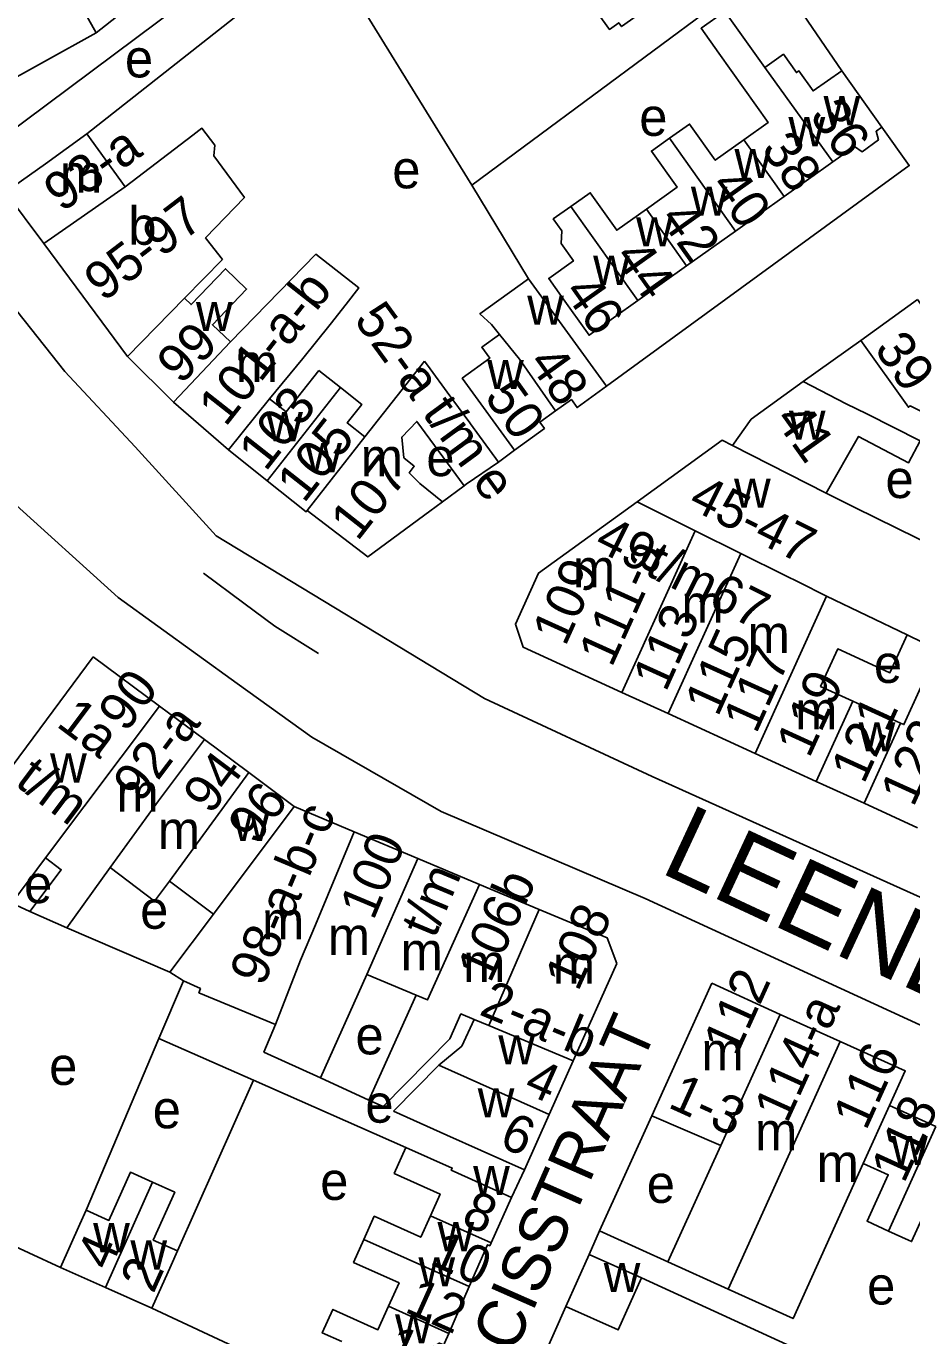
# Model space of a CAD drawing. Extents: x 161141 to 163125, y 381621 to 383200.
# Drawn here: x 162126.8 to 162220.2, y 381774.6 to 381912.6 of the extents above; entities that cross this region are included whole.
import ezdxf

# ---------------------------------------------------------------- set-up
doc = ezdxf.new("R2010")
doc.units = 0
for name, color, linetype in [('BLT_Basislijn', 7, 'Continuous'), ('BLT_Bebouwing', 7, 'Continuous'), ('BLT_Centroide', 7, 'Continuous'), ('BLT_Huisnummer', 7, 'Continuous'), ('BLT_Huisnummer_ tussenligend', 7, 'Continuous'), ('BLT_Huisnummer_reeks', 7, 'Continuous'), ('BLT_Onderverdeling_panden', 7, 'Continuous'), ('BLT_Straatnaam', 7, 'Continuous'), ('BLT_Straatnaam_hoofdweg', 7, 'Continuous')]:
    doc.layers.add(name, color=color, linetype=linetype)

msp = doc.modelspace()

# ---------------------------------------------------------------- linework, layer by layer
at = {"layer": 'BLT_Basislijn'}
for p, q in [((162134.15, 381911.93), (162150.61, 381924.97)), ((162133.2, 381901.27), (162158.24, 381921.04)), ((162205.2, 381919.04), (162212.81, 381907.93)), ((162159.58, 381918.87), (162167.08, 381906.74)), ((162199.23, 381914.71), (162173.8, 381895.86)), ((162167.08, 381906.74), (162173.8, 381895.86)), ((162173.8, 381895.86), (162179.76, 381886.01)), ((162208.74, 381875.18), (162214.81, 381879.51)), ((162176.6, 381866.68), (162178.28, 381867.95)), ((162170.69, 381862.51), (162172.97, 381864.2)), ((162124.99, 381862.81), (162136.48, 381852.42)), ((162146.82, 381858.92), (162175.11, 381841.76)), ((162145.49, 381855), (162149.74, 381851.82)), ((162136.48, 381852.42), (162149.05, 381843.37)), ((162149.74, 381851.82), (162153, 381849.38)), ((162153, 381849.38), (162157.63, 381846.52)), ((162149.05, 381843.37), (162156.93, 381837.69)), ((162156.93, 381837.69), (162170.57, 381829.85)), ((162170.57, 381829.85), (162192.08, 381820.69)), ((162127.17, 381819.34), (162125.26, 381820.19)), ((162192.08, 381820.69), (162221.5, 381807.18)), ((162141.92, 381812.92), (162131.07, 381817.61)), ((162140.78, 381805.93), (162143.37, 381812.03)), ((162133.11, 381787.85), (162140.78, 381805.93)), ((162150.75, 381801.55), (162140.78, 381805.93)), ((162157.82, 381801.79), (162162.94, 381799.43)), ((162150.75, 381801.55), (162142.74, 381783.56)), ((162166.84, 381794.47), (162150.75, 381801.55)), ((162192.77, 381797.81), (162187.27, 381785.66)), ((162177.97, 381789.2), (162179.33, 381792.09)), ((162130.41, 381781.82), (162109.59, 381791.3)), ((162187.27, 381785.66), (162186.16, 381783.18)), ((162209.99, 381772.34), (162191.68, 381780.71)), ((162140.03, 381777.51), (162157.92, 381769.21)), ((162183.71, 381777.7), (162181.23, 381772.15))]:
    msp.add_line(p, q, dxfattribs=at)
for points in [[(162095.04, 381933.46), (162106.52, 381912.88), (162113.22, 381900.94), (162120.76, 381888.92), (162130.87, 381876.22), (162138.27, 381868.29), (162146.82, 381858.92)], [(162121.93, 381899.15), (162152.46, 381921.89), (162150.61, 381924.97)], [(162217.02, 381901.99), (162219.93, 381897.94), (162188, 381874.69)], [(162175.11, 381841.76), (162192.8, 381833.55), (162249.74, 381807.94), (162257.79, 381806.18), (162274.06, 381798.97)], [(162187.27, 381785.66), (162191.82, 381783.6), (162194.48, 381782.39)]]:
    msp.add_lwpolyline(points, dxfattribs=at)
at = {"layer": 'BLT_Bebouwing'}
for p, q in [((162212.81, 381907.93), (162217.02, 381901.99)), ((162133.2, 381901.27), (162137.23, 381895.68)), ((162211.88, 381898.34), (162206.73, 381894.68)), ((162124.62, 381895.15), (162128.65, 381889.71)), ((162206.73, 381894.68), (162201.59, 381891.03)), ((162201.59, 381891.03), (162196.44, 381887.37)), ((162128.65, 381889.71), (162137.46, 381877.82)), ((162147.48, 381888.03), (162143.48, 381883.95)), ((162196.44, 381887.37), (162191.29, 381883.72)), ((162160.54, 381883.33), (162158.86, 381881.18)), ((162214.81, 381879.51), (162220.8, 381883.81)), ((162137.46, 381877.82), (162142.34, 381872.99)), ((162159.93, 381874.54), (162157.64, 381876.33)), ((162168.8, 381877.34), (162162.52, 381869.34)), ((162148.11, 381867.98), (162152.21, 381864.72)), ((162169.36, 381861.53), (162170.69, 381862.51)), ((162211.16, 381863.41), (162214.19, 381861.92)), ((162222.97, 381857.6), (162214.19, 381861.92)), ((162219.71, 381848.47), (162222.96, 381846.9)), ((162133.84, 381846.18), (162140.85, 381840.97)), ((162189.63, 381842.4), (162194.51, 381840.18)), ((162140.85, 381840.97), (162145.58, 381837.45)), ((162213.96, 381841.51), (162219.02, 381839.19)), ((162194.51, 381840.18), (162203.69, 381835.98)), ((162145.58, 381837.45), (162150.28, 381833.98)), ((162203.69, 381835.98), (162210.12, 381833.04)), ((162150.28, 381833.98), (162155.06, 381830.38)), ((162210.12, 381833.04), (162215.19, 381830.73)), ((162215.19, 381830.73), (162220.8, 381828.16)), ((162155.06, 381830.38), (162161.38, 381827.73)), ((162161.38, 381827.73), (162168.08, 381824.92)), ((162128.83, 381824.98), (162125.26, 381820.19)), ((162135.64, 381823.95), (162131.07, 381817.61)), ((162168.08, 381824.92), (162174.6, 381822.19)), ((162141.92, 381812.92), (162146.53, 381819.06)), ((162143.37, 381812.03), (162141.92, 381812.92)), ((162162.72, 381812.7), (162157.82, 381801.79)), ((162167.92, 381810.52), (162162.72, 381812.7)), ((162189.1, 381813.86), (162184.48, 381803.58)), ((162199.09, 381811.76), (162194.07, 381800.68)), ((162206.3, 381808.49), (162199.09, 381811.76)), ((162212.65, 381805.62), (162206.3, 381808.49)), ((162184.48, 381803.58), (162181.94, 381797.92)), ((162194.07, 381800.68), (162192.77, 381797.81)), ((162222.72, 381796.67), (162217.85, 381798.88)), ((162181.94, 381797.92), (162179.33, 381792.09)), ((162192.77, 381797.81), (162200.04, 381794.66)), ((162200.04, 381794.66), (162194.48, 381782.39)), ((162177.97, 381789.2), (162175.82, 381784.41)), ((162186.16, 381783.18), (162183.71, 381777.7)), ((162191.68, 381780.71), (162186.16, 381783.18)), ((162135.14, 381779.7), (162130.41, 381781.82)), ((162140.03, 381777.51), (162135.14, 381779.7)), ((162173.52, 381779.79), (162171.35, 381774.87)), ((162171.35, 381774.87), (162169.17, 381769.92))]:
    msp.add_line(p, q, dxfattribs=at)
for points in [[(162115.41, 381909.1), (162119.78, 381911.54), (162123.36, 381913.53), (162130.92, 381917.74), (162134.15, 381911.93)], [(162199.23, 381914.71), (162197.22, 381917.47), (162196.04, 381916.64), (162195.78, 381917), (162189.58, 381912.59), (162189.29, 381912.99), (162188.3, 381912.29), (162187.12, 381913.92)], [(162202.49, 381900.66), (162205.04, 381902.47), (162199.86, 381909.77), (162197.98, 381912.41), (162200.49, 381914.18), (162204.69, 381908.28)], [(162134.15, 381911.93), (162123.25, 381905.87), (162118.88, 381903.44)], [(162204.69, 381908.28), (162206.66, 381909.67), (162208.03, 381907.74), (162208.29, 381907.92), (162209.79, 381905.81), (162212.81, 381907.93)], [(162133.2, 381901.27), (162128.81, 381898.11), (162124.62, 381895.15)], [(162137.23, 381895.68), (162144.36, 381901.13), (162145.32, 381901.87), (162146.7, 381900.08), (162146.58, 381898.97), (162149.8, 381894.56), (162145.71, 381890.32), (162145.82, 381890.18), (162147.48, 381888.03)], [(162194.64, 381900.81), (162196.75, 381902.31), (162199.46, 381898.5), (162202.49, 381900.66)], [(162217.02, 381901.99), (162216.43, 381901.56), (162216.68, 381900.64), (162214.96, 381899.39), (162214.16, 381899.96), (162211.88, 381898.34)], [(162192.2, 381893.35), (162195.44, 381895.65), (162192.74, 381899.46), (162194.64, 381900.81)], [(162184.25, 381893.64), (162186.28, 381895.08), (162189.08, 381891.13), (162192.2, 381893.35)], [(162184.25, 381893.64), (162182.38, 381892.32), (162183.27, 381891.07), (162183.22, 381889.71), (162184.51, 381887.89), (162181.9, 381886.04), (162183.25, 381884.14), (162186.15, 381880.06), (162191.29, 381883.72)], [(162148.35, 381879.37), (162157.34, 381888.59), (162161.88, 381885.04), (162160.54, 381883.33)], [(162143.48, 381883.95), (162144.17, 381883.29), (162147.82, 381887.06), (162150.03, 381884.93), (162146.42, 381881.17), (162148.35, 381879.37)], [(162176.7, 381880.14), (162175.85, 381881.19), (162174.64, 381882.33), (162179.76, 381886.01)], [(162179.76, 381886.01), (162188, 381874.69)], [(162214.81, 381879.51), (162219.84, 381872.46), (162220.02, 381872.6), (162225.18, 381870.05), (162228.78, 381872.62), (162220.8, 381883.81)], [(162152.46, 381873.35), (162155.95, 381877.62), (162158.86, 381881.18)], [(162178.28, 381867.95), (162172.78, 381875.52), (162175.68, 381877.63), (162174.83, 381878.8), (162176.7, 381880.14)], [(162157.64, 381876.33), (162154.21, 381871.99), (162152.46, 381873.35)], [(162168.8, 381877.34), (162169.39, 381876.53), (162171.2, 381874.05), (162173.57, 381870.82), (162173.64, 381870.72), (162176.6, 381866.68)], [(162208.74, 381875.18), (162203.26, 381871.21), (162201.28, 381868.44)], [(162221.09, 381868.94), (162215.45, 381871.76), (162213.29, 381872.84), (162208.74, 381875.18)], [(162162.52, 381869.34), (162160.65, 381870.81), (162162.18, 381872.76), (162159.93, 381874.54)], [(162182.63, 381872.08), (162184.29, 381873.28), (162184.9, 381872.44), (162188, 381874.69)], [(162142.34, 381872.99), (162148.11, 381867.98)], [(162178.28, 381867.95), (162181.45, 381870.23), (162180.97, 381870.89), (162182.63, 381872.08)], [(162170.69, 381862.51), (162168.29, 381864.45), (162167.19, 381865.56), (162167.71, 381866.25), (162166.62, 381867.14), (162166.4, 381869.33), (162167.98, 381870.98), (162172.97, 381864.2)], [(162211.16, 381863.41), (162214.59, 381869.39), (162219.84, 381866.61), (162221.09, 381868.94)], [(162201.28, 381868.44), (162200.19, 381868.99), (162191.22, 381862.51)], [(162172.97, 381864.2), (162173.18, 381864.35), (162176.6, 381866.68)], [(162152.21, 381864.72), (162156.32, 381861.45), (162156.43, 381861.58)], [(162191.22, 381862.51), (162180.84, 381854.99), (162178.38, 381849.61), (162179.21, 381847.17), (162189.63, 381842.4)], [(162156.43, 381861.58), (162162.83, 381856.69), (162169.36, 381861.53)], [(162219.71, 381848.47), (162217.89, 381844.49), (162215.07, 381845.78)], [(162117.74, 381823.38), (162118.96, 381826.11), (162133.84, 381846.18)], [(162215.07, 381845.78), (162212.38, 381847), (162210.58, 381843.05), (162213.96, 381841.51)], [(162219.02, 381839.19), (162219.37, 381839.03), (162222.96, 381846.9)], [(162127.17, 381819.34), (162130.48, 381823.73), (162128.83, 381824.98)], [(162135.64, 381823.95), (162140.31, 381820.42), (162141.9, 381822.54)], [(162141.9, 381822.54), (162146.53, 381819.06)], [(162174.6, 381822.19), (162180.9, 381819.55)], [(162180.9, 381819.55), (162188.08, 381816.55), (162189.1, 381813.86)], [(162131.07, 381817.61), (162127.17, 381819.34)], [(162153.1, 381807.42), (162145.01, 381810.76), (162145.16, 381811.21), (162143.37, 381812.03)], [(162162.94, 381799.43), (162167.92, 381810.52)], [(162164.45, 381798.76), (162171.46, 381805.91), (162172.64, 381808.54), (162174.03, 381807.96)], [(162157.82, 381801.79), (162151.86, 381804.52), (162153.1, 381807.42)], [(162170.3, 381803.14), (162172.73, 381805.13), (162174.03, 381807.96)], [(162217.85, 381798.88), (162219.5, 381802.52), (162212.65, 381805.62)], [(162165.53, 381798.28), (162170.3, 381803.14)], [(162164.45, 381798.76), (162162.94, 381799.43)], [(162179.33, 381792.09), (162174.77, 381794.14), (162171.16, 381795.76), (162165.53, 381798.28)], [(162166.84, 381794.47), (162165.61, 381791.72), (162170.45, 381789.55), (162169.43, 381787.27)], [(162177.97, 381789.2), (162173.41, 381791.25), (162171.62, 381792.05), (162171.72, 381792.29), (162166.84, 381794.47)], [(162200.83, 381779.52), (162207.67, 381776.42), (162215.08, 381792.77)], [(162215.08, 381792.77), (162217.71, 381791.59), (162215.48, 381786.68), (162217.73, 381785.65)], [(162133.11, 381787.85), (162135.51, 381786.78), (162137.78, 381791.84), (162140.12, 381790.79)], [(162140.12, 381790.79), (162142.46, 381789.74), (162140.19, 381784.7), (162142.74, 381783.56)], [(162217.73, 381785.65), (162219.84, 381784.69), (162220.17, 381784.54), (162222.4, 381789.48), (162224.74, 381788.44)], [(162130.41, 381781.82), (162132.46, 381786.39), (162133.11, 381787.85)], [(162169.43, 381787.27), (162168.41, 381785), (162163.49, 381787.21), (162162.4, 381784.77)], [(162162.4, 381784.77), (162161.31, 381782.34), (162166.11, 381780.19), (162165, 381777.72)], [(162175.82, 381784.41), (162175.68, 381784.1), (162175.46, 381784.2), (162173.52, 381779.79)], [(162142.74, 381783.56), (162142.08, 381782.07), (162140.03, 381777.51)], [(162194.48, 381782.39), (162200.83, 381779.52)], [(162183.71, 381777.7), (162189.23, 381775.23), (162191.68, 381780.71)], [(162160.07, 381774), (162158.02, 381774.92), (162159.13, 381777.39), (162163.89, 381775.25), (162165, 381777.72)]]:
    msp.add_lwpolyline(points, dxfattribs=at)
at = {"layer": 'BLT_Onderverdeling_panden'}
for p, q in [((162211.88, 381898.34), (162204.69, 381908.28)), ((162201.59, 381891.03), (162194.64, 381900.81)), ((162206.73, 381894.68), (162202.49, 381900.66)), ((162128.65, 381889.71), (162137.23, 381895.68)), ((162191.29, 381883.72), (162184.25, 381893.64)), ((162196.44, 381887.37), (162192.2, 381893.35)), ((162137.46, 381877.82), (162143.48, 381883.95)), ((162148.35, 381879.37), (162142.34, 381872.99)), ((162159.93, 381874.54), (162152.21, 381864.72)), ((162152.46, 381873.35), (162148.11, 381867.98)), ((162162.52, 381869.34), (162156.43, 381861.58)), ((162211.16, 381863.41), (162201.28, 381868.44)), ((162197.34, 381859.45), (162191.22, 381862.51)), ((162189.63, 381842.4), (162197.34, 381859.45)), ((162202.15, 381857.05), (162197.34, 381859.45)), ((162194.51, 381840.18), (162202.15, 381857.05)), ((162203.69, 381835.98), (162211.21, 381852.55)), ((162211.21, 381852.55), (162219.71, 381848.47)), ((162128.83, 381824.98), (162140.85, 381840.97)), ((162210.12, 381833.04), (162213.96, 381841.51)), ((162219.02, 381839.19), (162215.19, 381830.73)), ((162141.9, 381822.54), (162150.28, 381833.98)), ((162146.53, 381819.06), (162155.06, 381830.38)), ((162157.29, 381817.93), (162161.38, 381827.73)), ((162162.72, 381812.7), (162168.08, 381824.92)), ((162175.57, 381807.31), (162180.9, 381819.55)), ((162155.72, 381814.19), (162157.29, 381817.93)), ((162155.72, 381814.19), (162153.1, 381807.42)), ((162200.04, 381794.66), (162206.3, 381808.49)), ((162175.57, 381807.31), (162184.48, 381803.58)), ((162200.83, 381779.52), (162212.65, 381805.62)), ((162217.85, 381798.88), (162215.08, 381792.77)), ((162217.73, 381785.65), (162222.72, 381796.67)), ((162140.12, 381790.79), (162135.14, 381779.7)), ((162169.43, 381787.27), (162175.82, 381784.41)), ((162162.4, 381784.77), (162173.52, 381779.79)), ((162165, 381777.72), (162171.35, 381774.87))]:
    msp.add_line(p, q, dxfattribs=at)
for points in [[(162176.7, 381880.14), (162178.83, 381877.52), (162182.63, 381872.08)], [(162202.15, 381857.05), (162206.84, 381854.75)], [(162206.84, 381854.75), (162208.28, 381854.05), (162211.21, 381852.55)], [(162135.64, 381823.95), (162140.73, 381831), (162145.58, 381837.45)], [(162167.92, 381810.52), (162169.13, 381810.01), (162174.6, 381822.19)], [(162174.03, 381807.96), (162175.57, 381807.31)], [(162170.3, 381803.14), (162181.94, 381797.92)]]:
    msp.add_lwpolyline(points, dxfattribs=at)

# ---------------------------------------------------------------- texts
at = {"layer": 'BLT_Centroide'}
for s, p in [('e', (162137.2, 381907.23)), ('w', (162210.89, 381902.19)), ('e', (162191.45, 381901.07)), ('w', (162207.19, 381899.97)), ('w', (162201.49, 381896.62)), ('m', (162130.35, 381895.09)), ('e', (162165.4, 381895.54)), ('w', (162196.89, 381892.66)), ('b', (162137.56, 381889.59)), ('w', (162191.12, 381889.41)), ('w', (162186.59, 381885.36)), ('w', (162144.69, 381880.5)), ('w', (162179.63, 381881.16)), ('m', (162148.89, 381875.14)), ('w', (162175.41, 381874.39)), ('w', (162207.23, 381869.05)), ('w', (162152.1, 381868.88)), ('w', (162156.22, 381865.62)), ('m', (162162.07, 381865.2)), ('e', (162168.99, 381865.21)), ('e', (162217.42, 381862.9)), ('w', (162201.45, 381861.88)), ('m', (162184.45, 381853.49)), ('m', (162195.89, 381849.75)), ('m', (162202.88, 381846.56)), ('e', (162216.2, 381843.42)), ('m', (162207.9, 381838.52)), ('w', (162214.59, 381836.19)), ('w', (162129.31, 381832.91)), ('m', (162136.31, 381829.86)), ('w', (162148.59, 381826.75)), ('m', (162140.67, 381825.92)), ('e', (162126.56, 381820.21)), ('e', (162138.81, 381817.51)), ('m', (162151.66, 381816.38)), ('m', (162158.6, 381814.75)), ('m', (162166.28, 381813.14)), ('m', (162172.87, 381811.9)), ('m', (162182.33, 381811.72)), ('e', (162161.52, 381804.27)), ('w', (162176.58, 381803.22)), ('m', (162198, 381802.6)), ('e', (162129.21, 381801.05)), ('w', (162174.41, 381797.62)), ('e', (162140.13, 381796.48)), ('e', (162162.56, 381797.07)), ('m', (162203.66, 381794.16)), ('w', (162218.02, 381792.61)), ('m', (162210.16, 381790.83)), ('e', (162157.8, 381788.93)), ('w', (162173.93, 381789.44)), ('e', (162192.24, 381788.62)), ('w', (162133.85, 381783.42)), ('w', (162170.17, 381783.53)), ('w', (162137.78, 381781.59)), ('w', (162168.16, 381779.81)), ('w', (162187.7, 381779.22)), ('e', (162215.48, 381777.91)), ('w', (162165.69, 381773.81))]:
    msp.add_text(s, height=4, dxfattribs=at).set_placement(p)
at = {"layer": 'BLT_Huisnummer'}
for s, rotation, p in [('36', 305.3777, (162209.33, 381903.17)), ('40', 305.3777, (162198.87, 381895.84)), ('44', 305.3773, (162188.74, 381888.33)), ('46', 305.3773, (162183.39, 381884.6)), ('99', 46.1213, (162143.1, 381874.75)), ('39', 305.5231, (162216.15, 381878.6)), ('48', 305.7216, (162179.64, 381877.13)), ('50', 305.7148, (162175.03, 381873.55)), ('103', 51.853, (162152.04, 381865.59)), ('41', 305.5231, (162205.63, 381871.17)), ('119', 65.439, (162209.37, 381835.38)), ('94', 53.0256, (162146.25, 381829.42)), ('96', 53.0256, (162150.98, 381826.22)), ('116', 65.6268, (162215.37, 381796.14)), ('6', 335.8444, (162176.52, 381794.66)), ('8', 335.8398, (162172.52, 381786.43)), ('4', 65.8455, (162135.58, 381781.34)), ('2', 65.8491, (162140.2, 381778.96)), ('12', 335.8406, (162166.57, 381777.19))]:
    msp.add_text(s, height=4, rotation=rotation, dxfattribs=at).set_placement(p)
at = {"layer": 'BLT_Huisnummer_ tussenligend'}
for s, rotation, p in [('38', 305.3777, (162204.21, 381899.67)), ('42', 305.3777, (162193.52, 381892.34)), ('105', 51.853, (162156.08, 381862.25)), ('113', 65.6398, (162194.25, 381842.36)), ('121', 65.4471, (162215.14, 381832.66)), ('4', 335.8455, (162179.11, 381800.31)), ('118', 65.6268, (162219.38, 381790.57)), ('10', 335.8398, (162169.2, 381782.21)), ('14', 335.8391, (162164.36, 381772.25))]:
    msp.add_text(s, height=4, rotation=rotation, dxfattribs=at).set_placement(p)
at = {"layer": 'BLT_Huisnummer_reeks'}
for s, rotation, p in [('93-a', 35.4032, (162130.53, 381892.94)), ('95-97', 37.3702, (162134.91, 381883.49)), ('101-a-b', 51.8741, (162147.81, 381870.3)), ('52-a t/m e', 306.1932, (162161.27, 381881.67)), ('107', 51.8504, (162161.73, 381858.25)), ('45-47', 333.4482, (162196.48, 381861.92)), ('49t/m67', 333.4499, (162186.55, 381857.58)), ('111-a', 65.6449, (162188.54, 381844.95)), ('109', 65.6449, (162183.65, 381847.17)), ('115', 65.6431, (162199.73, 381839.74)), ('117', 65.6388, (162203.78, 381837.95)), ('90', 53.0392, (162137.3, 381838.08)), ('123-a', 65.6433, (162220.36, 381830.22)), ('1a', 323.0299, (162129.84, 381838.93)), ('92-a', 53.0262, (162138.87, 381830.63)), ('t/m', 323.0316, (162125.47, 381832.73)), ('98-a-b-c', 67.3071, (162151.8, 381811.31)), ('100', 67.3085, (162163.41, 381818.29)), ('t/m', 67.3071, (162169.86, 381816.37)), ('106b', 65.8345, (162175.75, 381811.68)), ('108', 65.8396, (162184.99, 381810.79)), ('112', 65.6254, (162201.7, 381803.92)), ('2-a-b', 337.3655, (162174.44, 381808.51)), ('114-a', 65.5903, (162207.05, 381796.89)), ('1-3', 335.6234, (162194.35, 381798.74))]:
    msp.add_text(s, height=4, rotation=rotation, dxfattribs=at).set_placement(p)
at = {"layer": 'BLT_Straatnaam'}
msp.add_text('NARCISSTRAAT', height=4.9999, rotation=66.214, dxfattribs=at).set_placement((162172.54, 381759.67))
at = {"layer": 'BLT_Straatnaam_hoofdweg'}
msp.add_text('LEENDERWEG', height=8, rotation=335.0461, dxfattribs=at).set_placement((162193.45, 381823.52))

doc.saveas('drawing.dxf')
